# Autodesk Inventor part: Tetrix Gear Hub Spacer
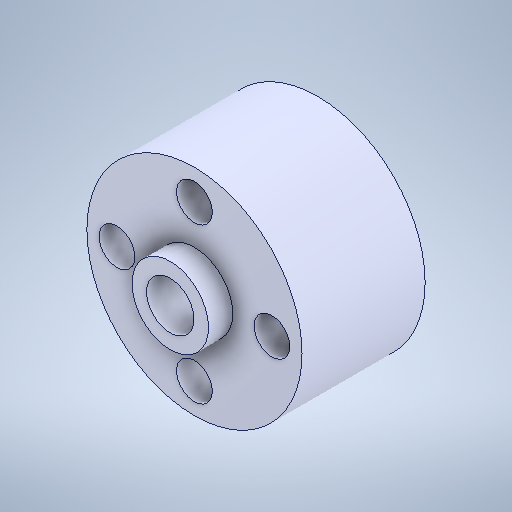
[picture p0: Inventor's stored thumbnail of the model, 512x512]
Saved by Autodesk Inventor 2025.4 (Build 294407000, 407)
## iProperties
Created: 2021-10
Part Number: Tetrix Gear Hub Spacer
Material: Genérico
Document SubType Name: Modeling
Designer: usuario
Density: 1 g/cm^3
Appearance: Valor por defecto
Author: usuario
Sending System: SolidWorks 2016
Last Author: LENOVO
Last Saved: 2021-10-22
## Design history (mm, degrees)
feature "Ø4.9 (4.9) Diameter Hole1"
node "Plane1"
node "Sólido1"
